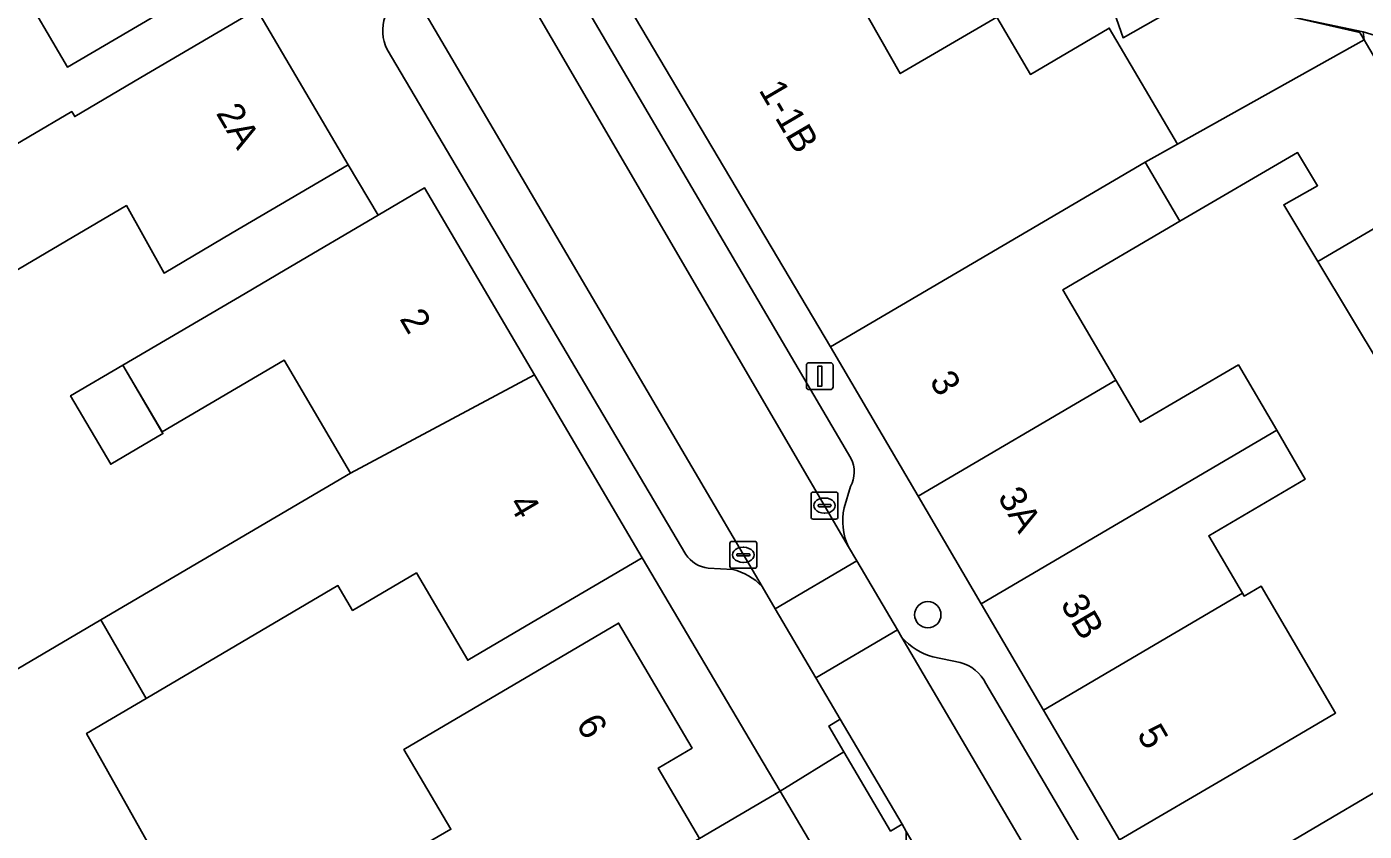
# Model space of a CAD drawing. Extents: x 159716 to 160783, y 383290 to 384031.
# Drawn here: x 160111.85 to 160161.56, y 383432.35 to 383462.26 of the extents above; entities that cross this region are included whole.
import ezdxf

# ---------------------------------------------------------------- set-up
doc = ezdxf.new("R2010")
doc.units = 0
for name, color, linetype in [('IMGEO_Boom', 7, 'Continuous'), ('IMGEO_Erf', 7, 'Continuous'), ('IMGEO_Kolk', 7, 'Continuous'), ('IMGEO_Lichtmast', 7, 'Continuous'), ('IMGEO_Muur', 7, 'Continuous'), ('IMGEO_Pand', 7, 'Continuous'), ('IMGEO_Pand_nummerreeks', 7, 'Continuous'), ('IMGEO_Parkeervlak_open', 7, 'Continuous'), ('IMGEO_Rijbaan_lokaal_open', 7, 'Continuous'), ('IMGEO_Voetpad_open', 7, 'Continuous')]:
    doc.layers.add(name, color=color, linetype=linetype)

msp = doc.modelspace()

# ---------------------------------------------------------------- linework, layer by layer
at = {"layer": 'IMGEO_Boom'}
msp.add_circle((160145.34, 383440.4), 0.489, dxfattribs=at)
at = {"layer": 'IMGEO_Erf'}
for points in [[(160146.213, 383465.64), (160140.569, 383467.11), (160144.314, 383460.514), (160147.9, 383462.618)], [(160158.69, 383462.666), (160155.381, 383463.43), (160152.601, 383461.851), (160151.748, 383464.302), (160151.214, 383464.432), (160147.9, 383462.618), (160149.152, 383460.484), (160152.084, 383462.205), (160154.616, 383457.887), (160161.558, 383461.772), (160161.518, 383462.068)], [(160115.422, 383449.678), (160116.914, 383447.135), (160114.971, 383445.995), (160113.479, 383448.538)], [(160121.757, 383423.202), (160127.533, 383426.603), (160125.087, 383430.973), (160127.616, 383432.426), (160125.869, 383435.396), (160133.846, 383440.089), (160136.58, 383435.441), (160135.323, 383434.702), (160136.858, 383432.085), (160139.85, 383433.844), (160139.22, 383434.91), (160134.723, 383442.518), (160130.414, 383439.984), (160128.242, 383438.706), (160126.331, 383441.956), (160123.961, 383440.562), (160123.419, 383441.485), (160116.287, 383437.29), (160114.078, 383435.99), (160116.849, 383431.044), (160117.085, 383431.183)]]:
    msp.add_lwpolyline(points, close=True, dxfattribs=at)
for points in [[(160108.721, 383456.279), (160113.525, 383459.105), (160113.635, 383458.918), (160116.096, 383460.366), (160120.405, 383462.901), (160119.544, 383464.378), (160116.981, 383462.87), (160113.362, 383460.758), (160111.515, 383463.912)], [(160107.952, 383436.294), (160114.61, 383440.211), (160123.885, 383445.667), (160121.415, 383449.865), (160116.881, 383447.198), (160115.422, 383449.678), (160119.97, 383452.346), (160121.462, 383453.227), (160124.909, 383455.253), (160123.801, 383457.127), (160119.492, 383454.592), (160116.953, 383453.098), (160115.556, 383455.612), (160113.326, 383454.3), (160110.771, 383452.796)], [(160162.226, 383449.555), (160159.839, 383453.531), (160158.572, 383455.641), (160159.829, 383456.349), (160159.082, 383457.579), (160154.709, 383455.03), (160150.36, 383452.478), (160152.327, 383449.124), (160153.248, 383447.554), (160156.882, 383449.686), (160158.307, 383447.256), (160159.371, 383445.442), (160155.781, 383443.335), (160157.036, 383441.197), (160157.096, 383441.094), (160157.726, 383441.464), (160160.495, 383436.745), (160156.783, 383434.567), (160152.47, 383432.037), (160154.136, 383429.2), (160158.445, 383431.737), (160163.493, 383434.709)]]:
    msp.add_lwpolyline(points, dxfattribs=at)
at = {"layer": 'IMGEO_Kolk'}
for p, q in [((160141.001, 383444.032), (160141.001, 383444.884)), ((160141.076, 383444.958), (160141.928, 383444.958)), ((160141.489, 383444.738), (160141.514, 383444.738)), ((160142.002, 383444.884), (160142.002, 383444.032)), ((160141.26, 383444.452), (160141.26, 383444.464)), ((160141.698, 383444.415), (160141.3, 383444.415)), ((160141.303, 383444.501), (160141.701, 383444.501)), ((160141.512, 383444.178), (160141.487, 383444.178)), ((160141.744, 383444.464), (160141.744, 383444.452)), ((160141.928, 383443.958), (160141.076, 383443.958)), ((160137.984, 383442.201), (160137.984, 383443.053)), ((160138.059, 383443.127), (160138.911, 383443.127)), ((160138.472, 383442.907), (160138.497, 383442.907)), ((160138.985, 383443.053), (160138.985, 383442.201)), ((160138.243, 383442.621), (160138.243, 383442.633)), ((160138.681, 383442.584), (160138.283, 383442.584)), ((160138.286, 383442.67), (160138.684, 383442.67)), ((160138.495, 383442.347), (160138.47, 383442.347)), ((160138.727, 383442.633), (160138.727, 383442.621)), ((160138.911, 383442.127), (160138.059, 383442.127))]:
    msp.add_line(p, q, dxfattribs=at)
for points in [[(160141.001, 383444.032), (160141.001, 383444.884)], [(160141.076, 383444.958), (160141.928, 383444.958)], [(160142.002, 383444.884), (160142.002, 383444.032)], [(160141.928, 383443.958), (160141.076, 383443.958)], [(160137.984, 383442.201), (160137.984, 383443.053)], [(160138.059, 383443.127), (160138.911, 383443.127)], [(160138.985, 383443.053), (160138.985, 383442.201)], [(160138.911, 383442.127), (160138.059, 383442.127)]]:
    msp.add_lwpolyline(points, dxfattribs=at)
for centre, radius, start, end in [((160141.078, 383444.882), 0.0765, 91.552, 178.448), ((160141.078, 383444.882), 0.0765, 91.552, 178.448), ((160141.926, 383444.882), 0.0765, 1.552, 88.448), ((160141.926, 383444.882), 0.0765, 1.552, 88.448), ((160141.3, 383444.461), 0.0403, 85.8775, 175.7526), ((160141.297, 383444.451), 0.0366, 178.938, 274.7102), ((160141.701, 383444.458), 0.043, 264.8664, 352.4533), ((160141.705, 383444.463), 0.0386, 1.7309, 96.639), ((160141.078, 383444.034), 0.0765, 181.552, 268.448), ((160141.078, 383444.034), 0.0765, 181.552, 268.448), ((160141.926, 383444.034), 0.0765, 271.552, 358.448), ((160141.926, 383444.034), 0.0765, 271.552, 358.448), ((160138.061, 383443.051), 0.0765, 91.552, 178.448), ((160138.061, 383443.051), 0.0765, 91.552, 178.448), ((160138.909, 383443.051), 0.0765, 1.552, 88.448), ((160138.909, 383443.051), 0.0765, 1.552, 88.448), ((160138.061, 383442.203), 0.0765, 181.552, 268.448), ((160138.061, 383442.203), 0.0765, 181.552, 268.448), ((160138.283, 383442.63), 0.0403, 85.8775, 175.7526), ((160138.28, 383442.62), 0.0366, 178.938, 274.7102), ((160138.684, 383442.627), 0.043, 264.8664, 352.4533), ((160138.688, 383442.632), 0.0386, 1.7309, 96.639), ((160138.909, 383442.203), 0.0765, 271.552, 358.448), ((160138.909, 383442.203), 0.0765, 271.552, 358.448)]:
    msp.add_arc(centre, radius, start, end, dxfattribs=at)
for centre, major_axis, ratio, start_param, end_param in [((160141.488, 383444.458), (-0.387, 0.002), 0.722429, 4.712389, 7.853982), ((160141.513, 383444.458), (-0.39, 0.002), 0.717154, 1.570796, 4.712389), ((160138.471, 383442.627), (-0.387, 0.002), 0.722429, 4.712389, 7.853982), ((160138.496, 383442.627), (-0.39, 0.002), 0.717154, 1.570796, 4.712389)]:
    msp.add_ellipse(centre, major_axis=major_axis, ratio=ratio, start_param=start_param, end_param=end_param, dxfattribs=at)
at = {"layer": 'IMGEO_Lichtmast'}
for p, q in [((160140.828, 383448.87), (160140.828, 383449.67)), ((160140.828, 383449.67), (160140.828, 383448.87)), ((160140.928, 383449.77), (160141.718, 383449.77)), ((160141.718, 383449.77), (160140.928, 383449.77)), ((160141.818, 383449.67), (160141.818, 383448.87)), ((160141.818, 383448.87), (160141.818, 383449.67)), ((160141.718, 383448.77), (160140.928, 383448.77)), ((160140.928, 383448.77), (160141.718, 383448.77))]:
    msp.add_line(p, q, dxfattribs=at)
msp.add_lwpolyline([(160141.248, 383449.645), (160141.398, 383449.645), (160141.398, 383448.895), (160141.248, 383448.895), (160141.248, 383449.645)], dxfattribs=at)
for centre, start, end in [((160140.928, 383449.67), 90, 180), ((160140.928, 383449.67), 90, 180), ((160141.718, 383449.67), 0, 90), ((160141.718, 383449.67), 360, 90), ((160140.928, 383448.87), 180, 270), ((160140.928, 383448.87), 180, 270), ((160141.718, 383448.87), 270, 0), ((160141.718, 383448.87), 270, 0)]:
    msp.add_arc(centre, 0.1, start, end, dxfattribs=at)
at = {"layer": 'IMGEO_Muur'}
msp.add_lwpolyline([(160158.69, 383462.666), (160161.396, 383462.049), (160161.558, 383461.772)], dxfattribs=at)
at = {"layer": 'IMGEO_Pand'}
for points in [[(160103.922, 383475.636), (160101.824, 383466.826), (160102.051, 383466.78), (160102.458, 383466.683), (160104.842, 383466.115), (160106.899, 383462.618), (160107.52, 383461.562), (160111.515, 383463.912), (160113.362, 383460.758), (160116.981, 383462.87), (160119.544, 383464.378), (160121.29, 383465.405), (160117.657, 383471.587), (160115.993, 383472.788), (160107.52, 383470.974), (160108.363, 383474.524)], [(160152.084, 383462.205), (160149.152, 383460.484), (160147.9, 383462.618), (160144.314, 383460.514), (160140.569, 383467.11), (160134.554, 383465.065), (160134.474, 383465.095), (160133.941, 383463.347), (160134.037, 383463.318), (160141.723, 383450.354), (160153.423, 383457.22), (160154.616, 383457.887)], [(160151.748, 383464.302), (160152.601, 383461.851), (160155.381, 383463.43)], [(160113.326, 383454.3), (160115.556, 383455.612), (160116.953, 383453.098), (160119.492, 383454.592), (160123.801, 383457.127), (160120.405, 383462.901), (160116.096, 383460.366), (160113.635, 383458.918), (160113.525, 383459.105), (160108.721, 383456.279), (160109.958, 383454.177), (160110.771, 383452.796)], [(160159.839, 383453.531), (160164.715, 383456.391), (160161.646, 383461.623), (160161.558, 383461.772), (160154.616, 383457.887), (160153.423, 383457.22), (160154.709, 383455.03), (160159.082, 383457.579), (160159.829, 383456.349), (160158.572, 383455.641)], [(160152.327, 383449.124), (160150.36, 383452.478), (160154.709, 383455.03), (160153.423, 383457.22), (160141.723, 383450.354), (160144.976, 383444.81)], [(160130.722, 383449.319), (160126.635, 383456.267), (160124.909, 383455.253), (160121.462, 383453.227), (160119.97, 383452.346), (160115.422, 383449.678), (160116.881, 383447.198), (160121.415, 383449.865), (160123.885, 383445.667)], [(160159.839, 383453.531), (160162.226, 383449.555), (160167.061, 383452.392), (160164.715, 383456.391)], [(160115.422, 383449.678), (160113.479, 383448.538), (160114.971, 383445.995), (160116.914, 383447.135)], [(160152.327, 383449.124), (160144.976, 383444.81), (160147.322, 383440.811), (160158.307, 383447.256), (160156.882, 383449.686), (160153.248, 383447.554)], [(160123.885, 383445.667), (160114.61, 383440.211), (160116.287, 383437.29), (160123.419, 383441.485), (160123.961, 383440.562), (160126.331, 383441.956), (160128.242, 383438.706), (160130.414, 383439.984), (160134.723, 383442.518), (160130.722, 383449.319)], [(160149.643, 383436.855), (160157.036, 383441.197), (160155.781, 383443.335), (160159.371, 383445.442), (160158.307, 383447.256), (160147.322, 383440.811)], [(160149.643, 383436.855), (160152.47, 383432.037), (160156.783, 383434.567), (160160.495, 383436.745), (160157.726, 383441.464), (160157.096, 383441.094), (160157.036, 383441.197)], [(160162.972, 383431.243), (160170.205, 383435.502), (160173.313, 383430.414), (160175.685, 383431.863), (160178.058, 383433.313), (160178.499, 383433.582), (160178.569, 383433.625), (160175.995, 383437.839), (160175.483, 383438.677), (160174.093, 383440.952), (160167.404, 383437.014), (160163.493, 383434.709), (160158.445, 383431.737), (160154.136, 383429.2), (160157.715, 383423.123), (160162.024, 383425.661), (160165.168, 383427.512)], [(160112.006, 383428.209), (160116.849, 383431.044), (160114.078, 383435.99), (160116.287, 383437.29), (160114.61, 383440.211), (160107.952, 383436.294)], [(160127.533, 383426.603), (160136.858, 383432.085), (160135.323, 383434.702), (160136.58, 383435.441), (160133.846, 383440.089), (160125.869, 383435.396), (160127.616, 383432.426), (160125.087, 383430.973)]]:
    msp.add_lwpolyline(points, close=True, dxfattribs=at)
at = {"layer": 'IMGEO_Parkeervlak_open'}
for points in [[(160128.582, 383466.6), (160142.398, 383442.928)], [(160139.179, 383441.454), (160125.493, 383464.755)], [(160142.48, 383446.217), (160131.488, 383464.944)], [(160125.249, 383461.408), (160136.342, 383442.643)], [(160142.236, 383444.376), (160142.466, 383445.163)], [(160137.18, 383442.131), (160138.09, 383442.083)], [(160144.376, 383439.558), (160144.463, 383439.409), (160154.695, 383421.991)], [(160146.543, 383438.631), (160145.533, 383438.837)], [(160154.91, 383425.268), (160147.497, 383437.842)]]:
    msp.add_lwpolyline(points, dxfattribs=at)
for centre, radius, start, end in [((160126.648, 383462.111), 1.566, 160.2709, 206.6964), ((160141.504, 383445.703), 1.103, 330.7059, 27.7721), ((160144.301, 383443.874), 2.125, 166.337, 206.4303), ((160137.325, 383443.309), 1.187, 214.1454, 263.0065), ((160137.587, 383439.954), 2.188, 43.2843, 76.6948), ((160146.157, 383441.126), 2.373, 221.3764, 254.7643), ((160146.151, 383437.186), 1.497, 25.9802, 74.8353)]:
    msp.add_arc(centre, radius, start, end, dxfattribs=at)
at = {"layer": 'IMGEO_Rijbaan_lokaal_open'}
for points in [[(160123.386, 383468.345), (160123.523, 383468.112), (160125.409, 383464.899), (160125.493, 383464.755), (160139.179, 383441.454), (160139.672, 383440.616), (160142.706, 383442.403), (160142.398, 383442.928), (160128.582, 383466.6)], [(160131.863, 383388.045), (160126.021, 383400.044), (160123.777, 383404.318), (160117.837, 383416.434), (160118.541, 383416.823), (160118.562, 383416.835), (160118.079, 383417.78), (160141.517, 383431.025), (160139.85, 383433.844), (160136.858, 383432.085), (160127.533, 383426.603), (160121.757, 383423.202), (160116.572, 383420.168), (160111.901, 383428.148), (160112.006, 383428.209), (160107.952, 383436.294)]]:
    msp.add_lwpolyline(points, dxfattribs=at)
for points in [[(160139.672, 383440.616), (160141.179, 383438.057), (160144.209, 383439.841), (160142.706, 383442.403)], [(160154.827, 383421.766), (160154.695, 383421.991), (160144.463, 383439.409), (160144.376, 383439.558), (160144.209, 383439.841), (160141.179, 383438.057), (160142.089, 383436.513), (160144.387, 383432.61), (160144.542, 383432.347), (160162.154, 383402.443), (160164.188, 383398.824), (160164.476, 383398.312), (160167.564, 383400.16), (160156.794, 383418.421), (160156.731, 383418.528)]]:
    msp.add_lwpolyline(points, close=True, dxfattribs=at)
at = {"layer": 'IMGEO_Voetpad_open'}
for points in [[(160123.027, 383470.751), (160115.993, 383472.788), (160117.657, 383471.587), (160121.29, 383465.405), (160119.544, 383464.378), (160120.405, 383462.901), (160123.801, 383457.127), (160124.909, 383455.253), (160126.635, 383456.267), (160130.722, 383449.319), (160134.723, 383442.518), (160139.22, 383434.91), (160139.85, 383433.844), (160142.224, 383435.301), (160141.659, 383436.26), (160142.089, 383436.513), (160141.179, 383438.057), (160139.672, 383440.616), (160139.179, 383441.454)], [(160184.751, 383376.839), (160181.49, 383382.38), (160180.303, 383384.395), (160179.08, 383386.472), (160175.446, 383392.621), (160174.289, 383394.585), (160173.041, 383396.705), (160157.715, 383423.123), (160154.136, 383429.2), (160152.47, 383432.037), (160149.643, 383436.855), (160147.322, 383440.811), (160144.976, 383444.81), (160141.723, 383450.354), (160134.037, 383463.318), (160133.941, 383463.347), (160134.474, 383465.095), (160134.554, 383465.065), (160140.569, 383467.11), (160128.252, 383470.363)], [(160128.252, 383470.363), (160140.569, 383467.11), (160146.213, 383465.64), (160151.214, 383464.432), (160151.748, 383464.302), (160155.381, 383463.43), (160158.69, 383462.666), (160161.518, 383462.068), (160162.085, 383461.897), (160163.431, 383462.189), (160165.382, 383462.612), (160171.131, 383461.254), (160171.178, 383461.464)], [(160131.488, 383464.944), (160142.48, 383446.217)], [(160136.342, 383442.643), (160125.249, 383461.408)], [(160142.466, 383445.163), (160142.236, 383444.376)], [(160142.398, 383442.928), (160142.706, 383442.403), (160144.209, 383439.841), (160144.376, 383439.558)], [(160138.09, 383442.083), (160137.18, 383442.131)], [(160145.533, 383438.837), (160146.543, 383438.631)], [(160147.497, 383437.842), (160154.91, 383425.268)], [(160144.335, 383430.23), (160144.552, 383430.979), (160144.542, 383432.347), (160144.387, 383432.61), (160143.958, 383432.357), (160142.224, 383435.301), (160139.85, 383433.844), (160141.517, 383431.025), (160118.079, 383417.78), (160118.562, 383416.835), (160118.607, 383416.738), (160125.235, 383420.608), (160127.695, 383421.598), (160129.968, 383422.965), (160129.891, 383423.096), (160141.981, 383430.194), (160146.336, 383422.776), (160147.114, 383421.48), (160151.18, 383414.554), (160154.12, 383409.513), (160157.37, 383403.997), (160157.663, 383403.476), (160160.96, 383397.915), (160164.204, 383392.444)]]:
    msp.add_lwpolyline(points, dxfattribs=at)
for points in [[(160163.431, 383462.189), (160162.085, 383461.897), (160161.518, 383462.068), (160161.558, 383461.772), (160161.646, 383461.623), (160164.715, 383456.391), (160167.061, 383452.392), (160168.541, 383449.869), (160169.034, 383449.023), (160170.617, 383450.007)], [(160142.089, 383436.513), (160141.659, 383436.26), (160142.224, 383435.301), (160143.958, 383432.357), (160144.387, 383432.61)]]:
    msp.add_lwpolyline(points, close=True, dxfattribs=at)
for centre, radius, start, end in [((160126.648, 383462.111), 1.566, 160.2709, 206.6964), ((160141.504, 383445.703), 1.103, 330.7059, 27.7721), ((160144.301, 383443.874), 2.125, 166.337, 206.4303), ((160137.325, 383443.309), 1.187, 214.1454, 263.0065), ((160137.587, 383439.954), 2.188, 43.2843, 76.6948), ((160146.157, 383441.126), 2.373, 221.3764, 254.7643), ((160146.151, 383437.186), 1.497, 25.9802, 74.8353)]:
    msp.add_arc(centre, radius, start, end, dxfattribs=at)

# ---------------------------------------------------------------- texts
at = {"layer": 'IMGEO_Pand_nummerreeks'}
for s, rotation, p in [('1-1B', 300.3952, (160139.039, 383459.907)), ('2A', 300.4621, (160118.867, 383459.044)), ('2', 300.4666, (160125.689, 383451.405)), ('3', 300.4156, (160145.383, 383449.095)), ('4', 300.4666, (160129.734, 383444.529)), ('3A', 300.4001, (160147.916, 383444.779)), ('3B', 300.4001, (160150.25, 383440.801)), ('6', 300.4645, (160132.246, 383436.339)), ('5', 300.4001, (160153.091, 383435.958))]:
    msp.add_text(s, height=1, rotation=rotation, dxfattribs=at).set_placement(p)

doc.saveas('drawing.dxf')
